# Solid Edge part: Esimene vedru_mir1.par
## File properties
Author: Türk
Template: Iso Part.par
Last saved by: Türk
Revision: 2
Application: Solid Edge
Accuracy: 0,990
Username: Türk
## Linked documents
Esimene vedru.par
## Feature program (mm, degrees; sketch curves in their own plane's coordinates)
part copy "CopiedPart_1"
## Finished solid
Body 1: solid body, 7 faces, 18 edges, 12 vertices.
  Faces by surface: plane 4, torus 2, spline 1
  Edges by curve: circle 10, intersection 6, line 2
Bounding box of the edges (mm; curved faces can reach further): 103.000 x 103.000 x 270.000, from (-51.5, -51.5, 0) to (51.5, 51.5, 270).
Toroidal faces (ring radius, tube radius in mm): R45.5 r6 x2
Planar faces by outward normal: +z 1, -z 1, oblique 2
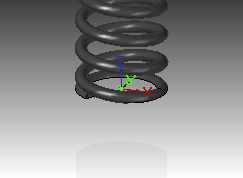
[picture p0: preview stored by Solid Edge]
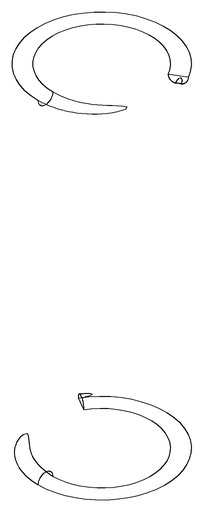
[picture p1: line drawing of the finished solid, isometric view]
